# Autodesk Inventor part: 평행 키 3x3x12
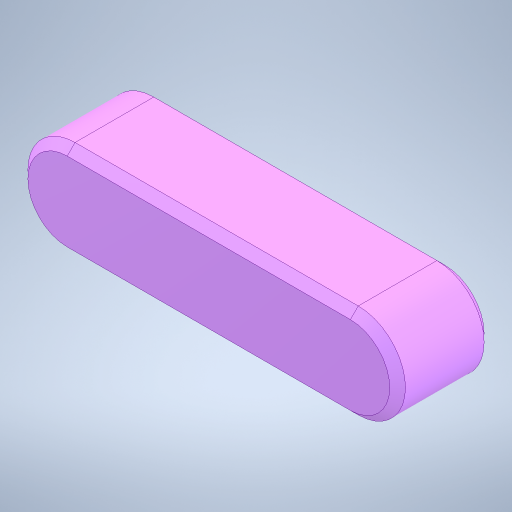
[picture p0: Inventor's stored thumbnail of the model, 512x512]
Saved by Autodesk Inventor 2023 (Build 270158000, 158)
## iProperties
Created: 2025-10
Part Number: 평행 키 3x3x12
Material: 강철, 연강
Description: 키 및 해당 키홈
Document SubType Name: Modeling
Designer: home
Density: 7.85 g/cm^3
Appearance: 기본값
Author: jhkim
Sending System: Autodesk Inventor 2026
Preprocessor: ST-DEVELOPER v20.1
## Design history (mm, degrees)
sketch "스케치1"
  geometry: 1 further point
  constraints: 1 other
feature "Solid1"
node "솔리드1"
